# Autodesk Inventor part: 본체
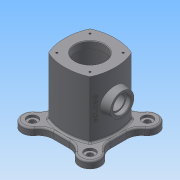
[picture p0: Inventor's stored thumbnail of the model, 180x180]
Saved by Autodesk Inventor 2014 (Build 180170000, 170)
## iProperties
Created: 2016-05
Part Number: 본체
Material: 일반
Document SubType Name: Modeling
Designer: 703-04
Density: 1 g/cm^3
Appearance: 기본값
Author: 703-04
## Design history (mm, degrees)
sketch "스케치1"
  geometry: L1 (-49, -49)-(49, -49); L2 (49, -49)-(49, 49); L3 (49, 49)-(-49, 49); L4 (-49, 49)-(-49, -49); L5 (-49, -49)-(49, 49); L6 (49, -49)-(-49, 49); L7 (0, 0)-(86.341, 86.341); L8 (86.341, 86.341)-(0, 0); L9 (0, 0)-(-73.669, -73.669); L10 (0, 0)-(78.413, -78.413); L11 (0, 0)-(-77.587, 77.587); C1 r 70 at (0, 0); C2 r 18 at (-49, 49); C3 r 18 at (49, 49); C4 r 18 at (49, -49); C5 r 18 at (-49, -49); 1 further point
  constraints: 22 end point, 5 centre point, 5 coincident, 3 perpendicular, 3 point on line, 2 midpoint, 2 parallel, 1 horizontal
  dimensions: "d0" = 98 distance of L1.end L2.end; "d1" = 98 distance of L2.end L3.end; "d2" = 140 diameter of C1; "d3" = 36 diameter of C2; "d4" = 36 diameter of C5; "d5" = 36 diameter of C4; "d6" = 36 diameter of C3
extrude "돌출1" new body sketch "스케치1" distance "d7" = 12; taper "d8" = 0 deg
fillet "모깎기1" dims "d9" = 25
fillet "모깎기2" dims "d10" = 25
sketch "스케치2"
  geometry: A1 r 18 centre (49, 49) between (59.465, 34.355) and (34.355, 59.465) reference; A2 r 18 centre (-49, 49) between (-34.355, 59.465) and (-59.465, 34.355) reference; A3 r 18 centre (-49, -49) between (-59.465, -34.355) and (-34.355, -59.465) reference; A4 r 18 centre (49, -49) between (34.355, -59.465) and (59.465, -34.355) reference; 1 further point
hole "구멍1" sketch "스케치2" at (-49, 49), (49, 49), (49, -49), (-49, -49) diameter "d11" = 10; stored, may be unused: countersink angle "d15" = 90 deg, drill point angle "d17" = 118 deg; dims "d12" = 6, "d13" = 4, "d14" = 2, "d16" = 8
sketch "스케치3"
  geometry: C1 r 5 at (49, -49) reference; C2 r 5 at (-49, 49) reference; C3 r 5 at (49, 49) reference; C4 r 5 at (-49, -49) reference; 1 further point
hole "구멍2" sketch "스케치3" at (-49, 49), (49, 49), (-49, -49), (49, -49) diameter "d18" = 18; stored, may be unused: countersink angle "d22" = 90 deg, drill point angle "d24" = 0 deg; dims "d19" = 6, "d20" = 4, "d21" = 2, "d23" = 4
sketch "스케치4"
  geometry: L1 (-14.014, -49)-(14.014, -49) reference; L2 (0, 0)-(0, 175.452); L3 (0, 0)-(-193.593, 0); L4 (0, 0)-(0, -167.329); L5 (0, 0)-(139.982, 0); L6 (-43, 71.102)-(-43, -80.052); L7 (-79.182, 43)-(71.724, 43); L8 (43, 77.318)-(43, -80.052); L9 (66.752, -43)-(-90.867, -43); L10 (-49, 49)-(49, -49); L11 (49, 49)-(-49, -49); L12 (0, 0)-(-35.355, 35.355); L13 (-49, -49)-(49, 49); L14 (0, 0)-(35.355, -35.355); L15 (-35.355, -35.355)-(0, 0); L16 (0, 0)-(35.355, 35.355); A1 r 18 centre (49, 49) between (59.465, 34.355) and (34.355, 59.465) reference; A2 r 18 centre (-49, 49) between (-34.355, 59.465) and (-59.465, 34.355) reference; A3 r 18 centre (-49, -49) between (-59.465, -34.355) and (-34.355, -59.465) reference; A4 r 18 centre (49, -49) between (34.355, -59.465) and (59.465, -34.355) reference; A5 r 40 centre (0, 0) between (-28.284, 28.284) and (28.284, 28.284); 4 further points; 4 other entities
  constraints: 30 end point, 7 perpendicular, 4 point on circle, 4 point on line, 3 coincident, 1 centre point, 16 other
  dimensions: "d25" = 80 diameter of A5; "d26" = 43 distance between parallel lines of L2 L6; "d27" = 43 distance between parallel lines of L8 L2; "d28" = 43 distance between parallel lines of L3 L9; "d29" = 43 distance between parallel lines of L3 L7; "d31" = 50 distance of L12.end L12.start; "d32" = 45 deg angle of L12 L2; "d33" = 50 distance of L14.end L12.start; "d34" = 45 deg angle of L5 L14; "d35" = 50 distance of L15.start L12.start; "d36" = 45 deg angle of L4 L15; "d37" = 50 distance of L16.end L12.start; "d38" = 45 deg angle of L7 L16
extrude "돌출2" join sketch "스케치4" distance "d39" = 98; taper "d40" = 0 deg
sketch "스케치5"
  geometry: L1 (-35.355, 35.355)-(35.355, -35.355); L2 (35.355, 35.355)-(-35.355, -35.355); A1 r 40 centre (0, 0) between (-28.284, 28.284) and (28.284, 28.284); 3 further points; 1 other entity
  constraints: 4 end point, 4 point on circle, 4 point on line, 1 centre point, 1 coincident, 1 perpendicular, 1 other
  dimensions: "d41" = 80 diameter of A1
hole "구멍3" sketch "스케치5" at (-28.284, 28.284), (28.284, 28.284), (28.284, -28.284), (-28.284, -28.284) diameter "d42" = 3.242; stored, may be unused: countersink angle "d46" = 90 deg, drill point angle "d48" = 118 deg; dims "d43" = 7, "d44" = 4, "d45" = 2, "d47" = 10
sketch "스케치6" dims "d49" = 80
  geometry: L1 (-49, 49)-(49, -49); L2 (49, 49)-(-49, -49); C1 r 5 at (-49, 49) reference; C2 r 5 at (-49, -49) reference; C3 r 1.621 at (28.284, 28.284) reference; C4 r 1.621 at (28.284, -28.284) reference; C5 r 1.621 at (-28.284, -28.284) reference; A1 r 18 centre (49, -49) between (34.355, -59.465) and (59.465, -34.355) reference; A2 r 18 centre (49, 49) between (59.465, 34.355) and (34.355, 59.465) reference; 6 further points
  constraints: 4 coincident, 4 end point, 1 perpendicular, 1 point on line, 3 other
hole "구멍4" sketch "스케치6" at (-28.284, 28.284), (28.284, 28.284), (28.284, -28.284), (-28.284, -28.284) diameter "d50" = 3.242; stored, may be unused: countersink angle "d54" = 90 deg, drill point angle "d56" = 118 deg; dims "d51" = 7, "d52" = 4, "d53" = 2, "d55" = 10
sketch "스케치7"
  geometry: C1 r 25 at (0, 0); 1 further point
  constraints: 1 centre point, 1 coincident
  dimensions: "d57" = 50 diameter of C1
extrude "돌출3" cut sketch "스케치7" distance "d58" = 110; taper "d59" = 0 deg
sketch "스케치9"
  geometry: L1 (35.355, 110)-(-35.355, 110) reference; C1 r 20 at (0, 61); 2 further points
  constraints: 1 centre point, 1 coincident
  dimensions: "d66" = 49 distance from line of point (0, 61) L1; "d67" = 40 diameter of C1
extrude "돌출4" join sketch "스케치9" distance "d68" = 55; taper "d69" = 0 deg
fillet "모깎기3" dims "d80" = 3
fillet "모깎기4" dims "d81" = 3
sketch "스케치8"
  geometry: L1 (0, 12)-(35, 12); L2 (35, 12)-(35, 98); L3 (35, 98)-(0, 98); L4 (-25, 110)-(25, 110) reference; L5 (0, 0)-(0, 136.68); L6 (0, 98)-(0, 12)
  constraints: 10 end point, 2 perpendicular, 2 point on line, 1 horizontal, 1 parallel
  dimensions: "d60" = 12 distance from line of L1 L5.start; "d61" = 12 distance between parallel lines of L3 L4; "d64" = 35 distance between parallel lines of L5 L2
revolve "회전1" sketch "스케치8" stored, may be unused: angle "d65" = 90 deg
fillet "모깎기5" dims "d82" = 3
fillet "모깎기6" dims "d83" = 3
chamfer "모따기1" distance "d84" = 1; stored, may be unused: second distance "d85" = 2, angle "d86" = 45 deg
sketch "스케치13"
  geometry: L1 (36.653, 84.235)-(36.653, 61); L2 (55, 41)-(55, 81) reference; L3 (55, 81)-(36.653, 84.235); L4 (36.653, 61)-(55, 61); L5 (55, 81)-(55, 61); 1 further point
  constraints: 8 end point, 1 collinear, 1 midpoint, 1 vertical
  dimensions: "d90" = 100 deg angle of L1 L3
revolve "회전3" sketch "스케치13" stored, may be unused: angle "d91" = 90 deg
sketch "스케치14"
  geometry: C1 r 20 at (0, 0) reference; C2 r 12.5 at (0, 0); 1 further point
  constraints: 1 centre point, 1 coincident
  dimensions: "d92" = 25 diameter of C2
extrude "돌출7" cut sketch "스케치14" distance "d93" = 55; taper "d94" = 0 deg
sketch "스케치15"
  geometry: C1 r 12.5 at (0, 0) reference; C2 r 20 at (0, 0) reference; C3 r 15 at (0, 0); 1 further point
  constraints: 1 centre point, 1 coincident
  dimensions: "d95" = 30 diameter of C3
extrude "돌출8" cut sketch "스케치15" distance "d96" = 8; taper "d97" = 0 deg
chamfer "모따기3" distance "d98" = 1; stored, may be unused: second distance "d99" = 2, angle "d100" = 45 deg
chamfer "모따기4" distance "d101" = 1; stored, may be unused: second distance "d102" = 2, angle "d103" = 45 deg
fillet "모깎기7" dims "d104" = 3
sketch "스케치16"
  geometry: L1 (-34.353, -49)-(34.353, -49) reference; C1 r 20 at (0, 0) reference; 2 further points
  constraints: 1 other
  dimensions: "d105" = 49 distance from line of L1 point (29, 0); "d106" = 29 distance of point (29, 0) C1.centre
feature "엠보싱1" sketch "스케치16" dims "d0" = 98, "d1" = 98, "d2" = 140, "d3" = 36, "d4" = 36, "d5" = 36, "d6" = 36, "d107" = 0.5, "d108" = 0
node "솔리드1"
